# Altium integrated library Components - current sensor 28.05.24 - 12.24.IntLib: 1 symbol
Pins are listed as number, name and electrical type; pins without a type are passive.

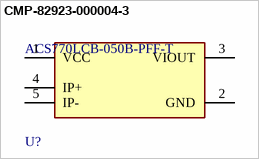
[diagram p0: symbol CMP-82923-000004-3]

## CMP-82923-000004-3
designator U?, comment ACS770LCB-050B-PFF-T
SENSOR CURRENT HALL 50A AC/DC; Max Input Voltage: 5.5V; Polarity: Bidirectional; Accuracy: 0.6%; Response Time: 4.6us; Sensitivity: 40mV/A; Number of Channels: 1; Max Supply Current: 15mA; Linearity: 1%; Frequency: 120kHz; Min Input Voltage: 4.5V
footprint FP-CB-5-PFF-MFG
pins: 1 VCC (power), 2 GND (power), 3 VIOUT, 4 IP+, 5 IP-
